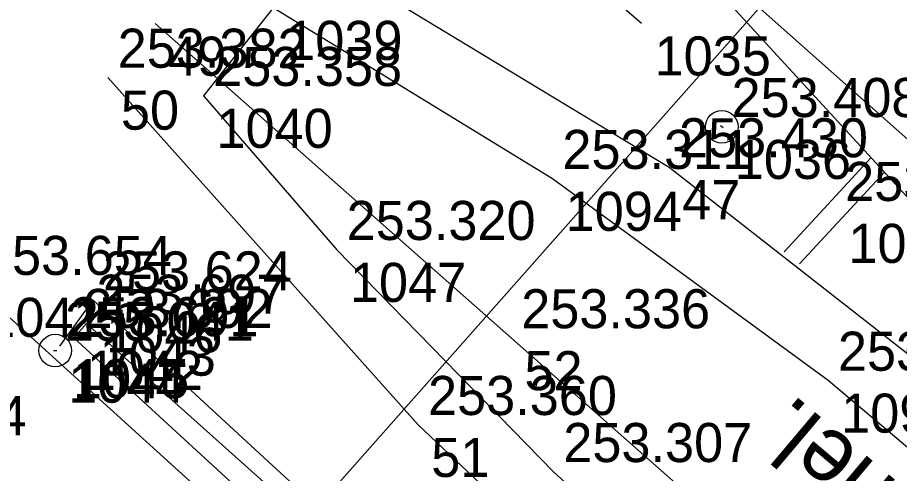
# Model space of a CAD drawing. Extents: x -496688 to -495455, y -1089309 to -1088026.
# Drawn here: x -496224.8 to -496197.72, y -1088460.89 to -1088446.9 of the extents above; entities that cross this region are included whole.
import ezdxf

# ---------------------------------------------------------------- set-up
doc = ezdxf.new("R2010")
doc.units = 0
for name, color, linetype in [('Vrstva 1', 7, 'Continuous'), ('Vrstva 16', 7, 'Continuous'), ('Vrstva 2', 7, 'Continuous'), ('Vrstva 23', 7, 'Continuous'), ('Vrstva 25', 7, 'Continuous'), ('Vrstva 36', 7, 'Continuous'), ('Vrstva 50', 7, 'Continuous'), ('Vrstva 51', 7, 'Continuous'), ('Vrstva 6', 7, 'Continuous'), ('Vrstva 60', 7, 'Continuous'), ('Vrstva 61', 7, 'Continuous'), ('Vrstva 7', 7, 'Continuous')]:
    doc.layers.add(name, color=color, linetype=linetype)

msp = doc.modelspace()

# ---------------------------------------------------------------- linework, layer by layer
at = {"layer": 'Vrstva 1'}
for points in [[(-496101.697, -1088535.642), (-496116.65, -1088522.36), (-496145.401, -1088496.824), (-496192.559, -1088454.988), (-496206.347, -1088442.759), (-496213.463, -1088436.447), (-496216.342, -1088433.89), (-496225.123, -1088426.139), (-496237.731, -1088415.01), (-496248.348, -1088406.17), (-496261.601, -1088395.991)], [(-496225.248, -1088439.85), (-496219.315, -1088442.699), (-496204.791, -1088451.487), (-496197.276, -1088457.363), (-496187.907, -1088465.601)], [(-496175.44, -1088476.59), (-496187.155, -1088463.683), (-496193.339, -1088456.911), (-496206.347, -1088442.759)], [(-496187.893, -1088475.966), (-496191.868, -1088472.437), (-496209.635, -1088456.735), (-496220.575, -1088447.084)], [(-496222.025, -1088448.74), (-496212.497, -1088459.397), (-496194.892, -1088476.055)]]:
    msp.add_lwpolyline(points, dxfattribs=at)
at = {"layer": 'Vrstva 16'}
msp.add_lwpolyline([(-496184.629, -1088475.67), (-496187.454, -1088475.604), (-496194.899, -1088468.574), (-496191.403, -1088465.223), (-496199.911, -1088458.038), (-496208.371, -1088451.846), (-496216.95, -1088446.6), (-496219.092, -1088449.299), (-496214.995, -1088454.026), (-496208.343, -1088460.841), (-496177.898, -1088488.575), (-496173.306, -1088483.846), (-496178.781, -1088476.82)], dxfattribs=at)
at = {"layer": 'Vrstva 2'}
for points in [[(-496213.854, -1088436.093), (-496206.347, -1088442.759), (-496192.559, -1088454.988)], [(-496206.347, -1088442.759), (-496193.339, -1088456.911)]]:
    msp.add_lwpolyline(points, dxfattribs=at)
at = {"layer": 'Vrstva 23'}
msp.add_lwpolyline([(-496181.425, -1088495.664), (-496185.899, -1088500.598), (-496230.62, -1088460.017), (-496226.16, -1088455.098), (-496181.425, -1088495.664)], dxfattribs=at)
at = {"layer": 'Vrstva 25'}
msp.add_line((-496223.693, -1088457.119), (-496223.593, -1088457.119), dxfattribs=at)
msp.add_circle((-496223.643, -1088457.119), 0.5, dxfattribs=at)
at = {"layer": 'Vrstva 36'}
for points in [[(-496205.64, -1088447.077), (-496209.648, -1088443.612)], [(-496223.499, -1088456.98), (-496222.478, -1088455.575), (-496197.873, -1088478.241)]]:
    msp.add_lwpolyline(points, dxfattribs=at)
at = {"layer": 'Vrstva 50'}
msp.add_line((-496203.136, -1088450.282), (-496203.218, -1088450.224), dxfattribs=at)
msp.add_circle((-496203.177, -1088450.253), 0.5, dxfattribs=at)
at = {"layer": 'Vrstva 51'}
msp.add_lwpolyline([(-496180.44, -1088495.367), (-496203.858, -1088474.361), (-496223.072, -1088456.725), (-496222.68, -1088456.29), (-496203.164, -1088473.734), (-496178.299, -1088495.921), (-496180.194, -1088498.089), (-496180.951, -1088498.955)], dxfattribs=at)
at = {"layer": 'Vrstva 6'}
msp.add_line((-496238.411, -1088487.695), (-496197.033, -1088440.957), dxfattribs=at)
at = {"layer": 'Vrstva 60'}
for p, q in [((-496220.575, -1088447.084), (-496220.575, -1088447.084)), ((-496220.575, -1088447.084), (-496220.575, -1088447.084)), ((-496205.64, -1088447.077), (-496205.64, -1088447.077)), ((-496205.64, -1088447.077), (-496205.64, -1088447.077)), ((-496222.025, -1088448.74), (-496222.025, -1088448.74)), ((-496222.025, -1088448.74), (-496222.025, -1088448.74)), ((-496219.092, -1088449.299), (-496219.092, -1088449.299)), ((-496219.092, -1088449.299), (-496219.092, -1088449.299)), ((-496203.177, -1088450.253), (-496203.177, -1088450.253)), ((-496203.177, -1088450.253), (-496203.177, -1088450.253)), ((-496204.791, -1088451.487), (-496204.791, -1088451.487)), ((-496204.791, -1088451.487), (-496204.791, -1088451.487)), ((-496208.371, -1088451.846), (-496208.371, -1088451.846)), ((-496208.371, -1088451.846), (-496208.371, -1088451.846)), ((-496199.689, -1088452.829), (-496199.689, -1088452.829)), ((-496199.689, -1088452.829), (-496199.689, -1088452.829)), ((-496214.995, -1088454.026), (-496214.995, -1088454.026)), ((-496214.995, -1088454.026), (-496214.995, -1088454.026)), ((-496222.478, -1088455.575), (-496222.478, -1088455.575)), ((-496222.478, -1088455.575), (-496222.478, -1088455.575)), ((-496222.68, -1088456.29), (-496222.68, -1088456.29)), ((-496222.68, -1088456.29), (-496222.68, -1088456.29)), ((-496223.072, -1088456.725), (-496223.072, -1088456.725)), ((-496223.072, -1088456.725), (-496223.072, -1088456.725)), ((-496209.635, -1088456.735), (-496209.635, -1088456.735)), ((-496209.635, -1088456.735), (-496209.635, -1088456.735)), ((-496223.643, -1088457.119), (-496223.643, -1088457.119)), ((-496223.643, -1088457.119), (-496223.643, -1088457.119)), ((-496223.499, -1088456.98), (-496223.499, -1088456.98)), ((-496223.499, -1088456.98), (-496223.499, -1088456.98)), ((-496199.911, -1088458.038), (-496199.911, -1088458.038)), ((-496199.911, -1088458.038), (-496199.911, -1088458.038)), ((-496212.497, -1088459.397), (-496212.497, -1088459.397)), ((-496212.497, -1088459.397), (-496212.497, -1088459.397)), ((-496208.343, -1088460.841), (-496208.343, -1088460.841)), ((-496208.343, -1088460.841), (-496208.343, -1088460.841))]:
    msp.add_line(p, q, dxfattribs=at)
at = {"layer": 'Vrstva 7'}
for p, q in [((-496201.264, -1088454.092), (-496198.591, -1088451.197)), ((-496200.788, -1088454.461), (-496198.183, -1088451.641))]:
    msp.add_line(p, q, dxfattribs=at)

# ---------------------------------------------------------------- texts
at = {"layer": 'Vrstva 16'}
msp.add_text('panel.', height=2, rotation=139.8189, dxfattribs=at).set_placement((-496195.45, -1088463.114))
at = {"layer": 'Vrstva 60'}
for s, p in [('1039', (-496216.55, -1088448.2)), ('1039', (-496216.55, -1088448.2)), ('49', (-496220.175, -1088448.684)), ('49', (-496220.175, -1088448.684)), ('1035', (-496205.24, -1088448.677)), ('1035', (-496205.24, -1088448.677)), ('50', (-496221.625, -1088450.34)), ('50', (-496221.625, -1088450.34)), ('1040', (-496218.692, -1088450.899)), ('1040', (-496218.692, -1088450.899)), ('1036', (-496202.777, -1088451.853)), ('1036', (-496202.777, -1088451.853)), ('47', (-496204.391, -1088453.087)), ('47', (-496204.391, -1088453.087)), ('1094', (-496207.971, -1088453.446)), ('1094', (-496207.971, -1088453.446)), ('1038', (-496199.289, -1088454.429)), ('1038', (-496199.289, -1088454.429)), ('1047', (-496214.595, -1088455.626)), ('1047', (-496214.595, -1088455.626)), ('1041', (-496225.76, -1088456.698)), ('1041', (-496225.76, -1088456.698)), ('1046', (-496222.078, -1088457.175)), ('1046', (-496222.078, -1088457.175)), ('1043', (-496222.28, -1088457.89)), ('1043', (-496222.28, -1088457.89)), ('1042', (-496222.672, -1088458.325)), ('1042', (-496222.672, -1088458.325)), ('52', (-496209.235, -1088458.335)), ('52', (-496209.235, -1088458.335)), ('1045', (-496223.099, -1088458.58)), ('1045', (-496223.099, -1088458.58)), ('1044', (-496223.243, -1088458.719)), ('1044', (-496223.243, -1088458.719)), ('1093', (-496199.511, -1088459.638)), ('1093', (-496199.511, -1088459.638)), ('51', (-496212.097, -1088460.997)), ('51', (-496212.097, -1088460.997))]:
    msp.add_text(s, height=1.2, dxfattribs=at).set_placement(p)
at = {"layer": 'Vrstva 61'}
for s, p in [('253.382', (-496221.725, -1088448.44)), ('253.382', (-496221.725, -1088448.44)), ('253.358', (-496218.792, -1088448.999)), ('253.358', (-496218.792, -1088448.999)), ('253.408', (-496202.877, -1088449.953)), ('253.408', (-496202.877, -1088449.953)), ('253.430', (-496204.491, -1088451.187)), ('253.430', (-496204.491, -1088451.187)), ('253.311', (-496208.071, -1088451.546)), ('253.311', (-496208.071, -1088451.546)), ('253.493', (-496199.389, -1088452.529)), ('253.493', (-496199.389, -1088452.529)), ('253.320', (-496214.695, -1088453.726)), ('253.320', (-496214.695, -1088453.726)), ('253.654', (-496225.86, -1088454.798)), ('253.654', (-496225.86, -1088454.798)), ('253.624', (-496222.178, -1088455.275)), ('253.624', (-496222.178, -1088455.275)), ('253.697', (-496222.38, -1088455.99)), ('253.697', (-496222.38, -1088455.99)), ('253.692', (-496222.772, -1088456.425)), ('253.692', (-496222.772, -1088456.425)), ('253.336', (-496209.335, -1088456.435)), ('253.336', (-496209.335, -1088456.435)), ('253.691', (-496223.199, -1088456.68)), ('253.691', (-496223.199, -1088456.68)), ('255.041', (-496223.343, -1088456.819)), ('255.041', (-496223.343, -1088456.819)), ('253.337', (-496199.611, -1088457.738)), ('253.337', (-496199.611, -1088457.738)), ('253.360', (-496212.197, -1088459.097)), ('253.360', (-496212.197, -1088459.097)), ('253.654', (-496230.32, -1088459.717)), ('253.654', (-496230.32, -1088459.717)), ('253.307', (-496208.043, -1088460.541)), ('253.307', (-496208.043, -1088460.541))]:
    msp.add_text(s, height=1.2, dxfattribs=at).set_placement(p)

doc.saveas('drawing.dxf')
